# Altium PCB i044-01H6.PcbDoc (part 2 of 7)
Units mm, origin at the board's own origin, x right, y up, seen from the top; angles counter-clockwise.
Board outline 42 x 29.01 mm, 8 copper layers (Top Layer, Mid-Layer 1, Mid-Layer 2, Mid-Layer 3, Mid-Layer 4, Mid-Layer 5, Mid-Layer 6, Bottom Layer), stack 1.474 mm thick; 235 components, 197 nets, 1006 pads, 1183 vias.
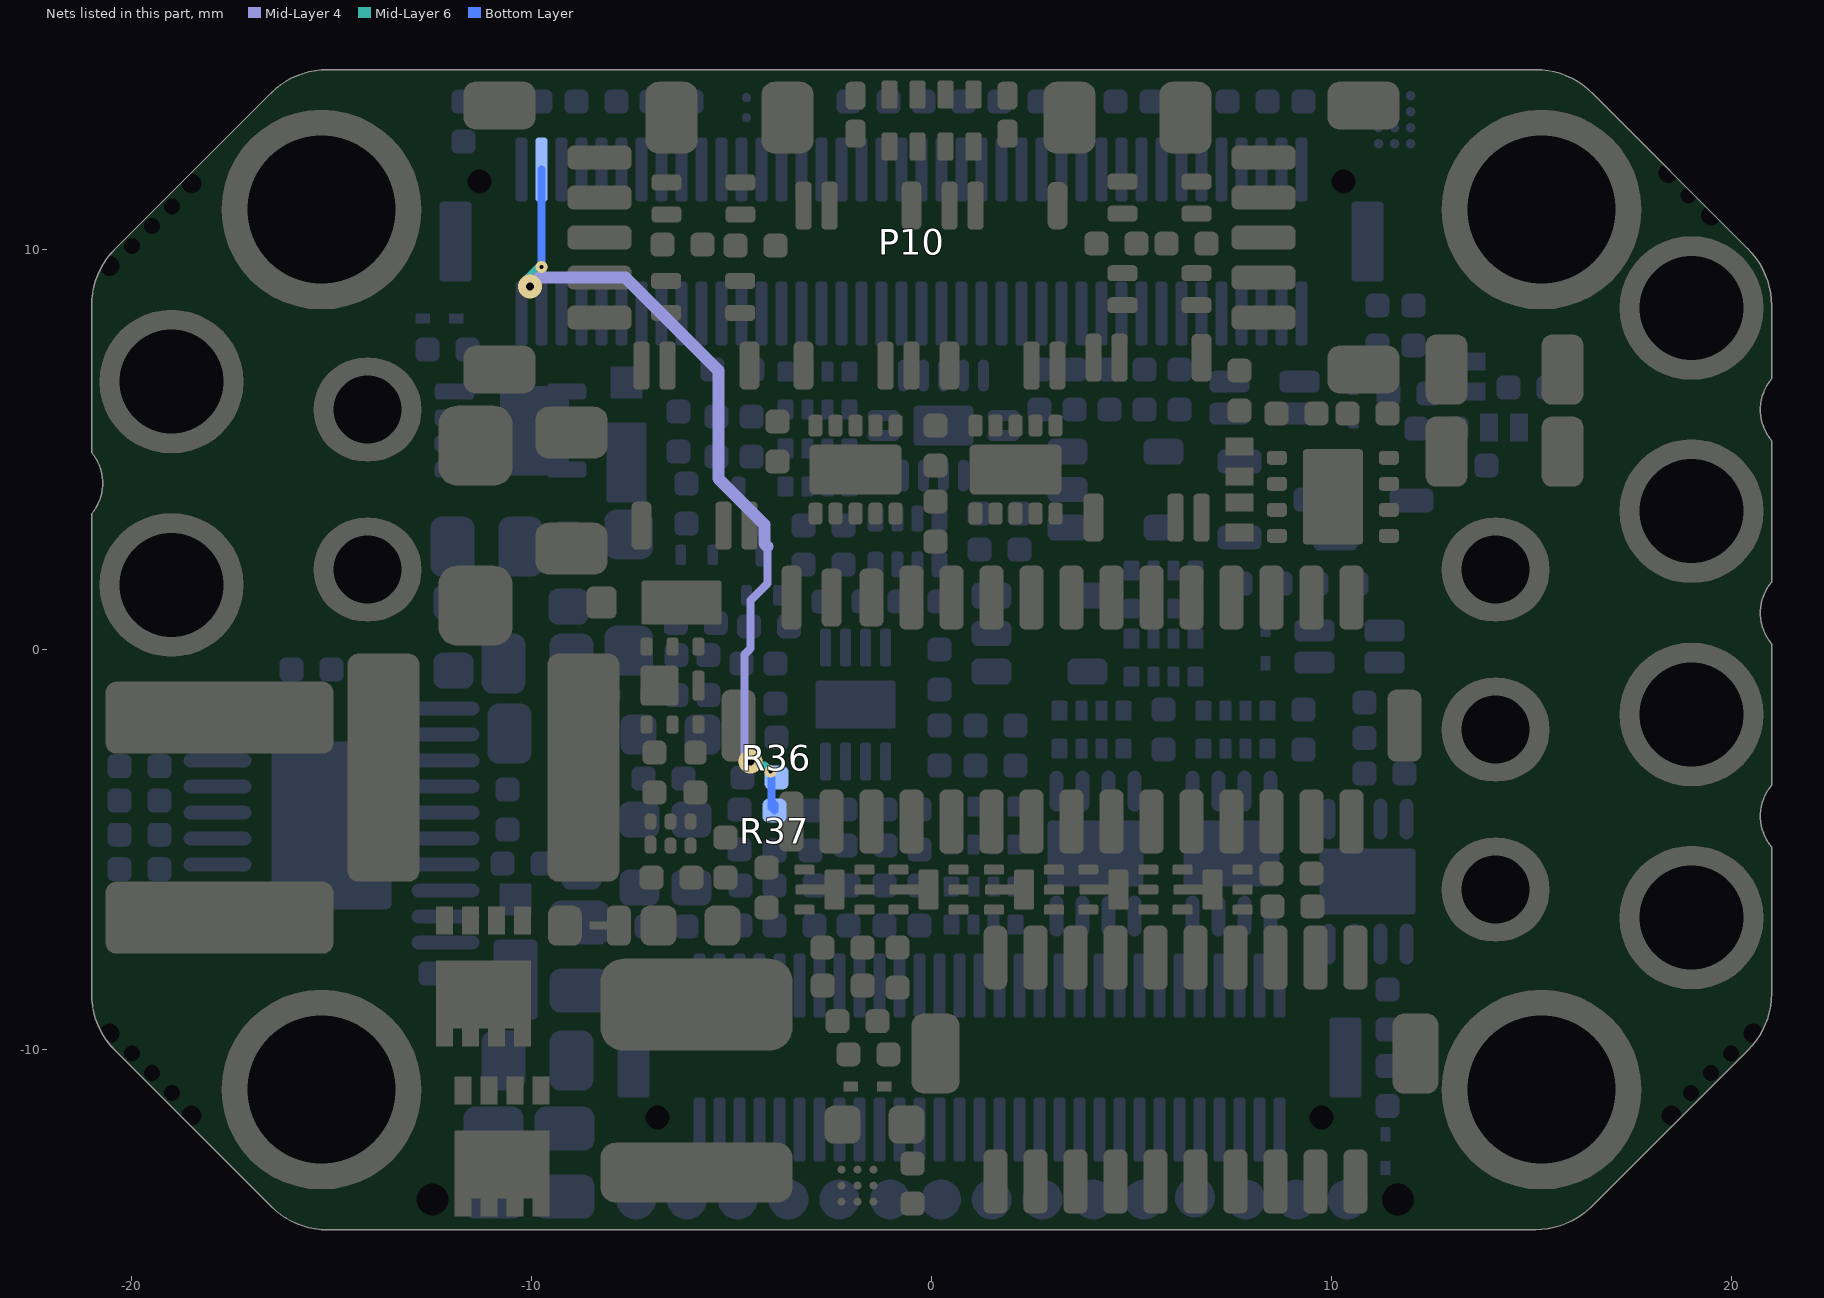
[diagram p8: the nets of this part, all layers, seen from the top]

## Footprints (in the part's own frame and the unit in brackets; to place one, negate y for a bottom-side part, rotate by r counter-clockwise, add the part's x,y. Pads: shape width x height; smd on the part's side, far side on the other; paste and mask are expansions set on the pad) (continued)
SOD923 [mm] "Doide SOD 923"
  rrect10% 0.36x0.25 smd mask+0.07: 1(-0.42,0) 2(0.42,0)
  silkscreen extent 0.9,-0.2 0.9,0.2, body extent -0.5,-0.3 0.5,0.3, height 0.4
SOD-882 [mm] "SOD-882, 2-Leads, Body 0,60x1,00mm, Pitch 0,65mm, IPC Medium Density"
  rect 0.45x0.7 smd mask+0.05: 1(-0.375,0) 2(0.375,0)
  body extent -0.55,-0.35 0.55,0.35, height 0.6
SOLDERPAD_2.6MM_EDGE [mm]
  round 3.6 hole 2.6 mask+0.05: 1(0,0)
  Multi-Layer region: -1.801,0 -1.801,1.899 -1.7,2 1.7,2 1.8,1.9 1.8,0
  body extent -0.01,-0.01 0.01,0.01, height 0.01
SOT23-3N [mm] "SOT23, 3-Leads, Body 2.9x1.3mm, Pitch 0.95mm, Lead Span 2.5mm, IPC Medium Density"
  rrect50% 1.1x0.6 smd: 1(-0.95,0.95) 2(-0.95,-0.95) 3(0.95,0)
  silkscreen extent -1.05,1.6 -0.85,1.8, body extent -1.23,-1.46 1.25,1.46, height 1
SOT23-5N [mm] "SOT23, 5-Leads, Body 2.9x1.6mm, Pitch 0.95mm, Lead Span 2.8mm, IPC Medium Density"
  rrect50% 1x0.65 smd mask+0.1: 1(-1.2,0.95) 3(-1.2,-0.95) 4(1.2,-0.95) 5(1.2,0.95)
  rrect50% 1x0.625 smd mask+0.1: 2(-1.2,0)
  silkscreen extent -1.35,1.58 -1.15,1.77, body extent -1.25,-1.5 1.25,1.5, height 1.05
SOT-723#1 [mm] "SOTFL, 3-Leads, Body 1,20x1,20mm, Pitch 0,40mm, IPC High Density"
  rrect50% 0.52x0.27 smd mask+0.07: 1(-0.49,0.4) 2(-0.49,-0.4)
  rrect65% 0.52x0.36 smd mask+0.07: 3(0.49,0)
  silkscreen extent -0.65,0.8 -0.45,1, body extent -0.59,-0.62 0.46,0.63, height 0.45
SOT-723#2 [mm] "SOTFL, 3-Leads, Body 1,20x1,20mm, Pitch 0,40mm, IPC High Density"
  rrect50% 0.52x0.27 smd mask+0.07: 1(-0.49,0.4) 2(-0.49,-0.4)
  rrect50% 0.52x0.36 smd mask+0.07: 3(0.49,0)
  silkscreen extent -0.65,0.8 -0.45,1, body extent -0.59,-0.62 0.46,0.63, height 0.45
TDK_ALT4523#1 [mm]
  rrect50% 1.2x0.41 smd: 1(-2,-1.35) 2(-2,-0.7) 4(2,1.35) 5(2,0.7)
  rrect50% 1.2x0.5 smd: 3(-2,1.35) 6(2,-1.35)
  silkscreen extent -3.4,-1.45 -3.15,-1.2, body extent -2.3,-1.6 2.3,1.6, height 2.9
TDK_ALT4523#2 [mm]
  rrect50% 1.2x0.39 smd: 1(-2,-1.35)
  rrect50% 1.2x0.41 smd: 2(-2,-0.7) 4(2,1.35) 5(2,0.7)
  rrect50% 1.2x0.5 smd: 3(-2,1.35)
  rrect50% 1.2x0.49 smd: 6(2,-1.35)
  silkscreen extent -3.4,-1.45 -3.15,-1.2, body extent -2.3,-1.6 2.3,1.6, height 2.9
TDK_ALT4523#3 [mm]
  rrect50% 1.2x0.4 smd: 1(-2,-1.35)
  rrect50% 1.2x0.41 smd: 2(-2,-0.7) 5(2,0.7)
  rrect50% 1.2x0.49 smd: 3(-2,1.35)
  rrect50% 1.2x0.39 smd: 4(2,1.35)
  rrect70% 1.19x0.5 smd: 6(2,-1.35)
  silkscreen extent -3.4,-1.45 -3.15,-1.2, body extent -2.3,-1.6 2.3,1.6, height 2.9
TDK_ALT4523#4 [mm]
  rrect50% 1.2x0.41 smd: 1(-2,-1.35) 2(-2,-0.7) 5(2,0.7)
  rrect50% 1.2x0.5 smd: 3(-2,1.35)
  rrect50% 1.2x0.39 smd: 4(2,1.35)
  rrect50% 1.19x0.5 smd: 6(2,-1.35)
  silkscreen extent -3.4,-1.45 -3.15,-1.2, body extent -2.3,-1.6 2.3,1.6, height 2.9
TSOP20_065P_EP [mm] "TSOP, 20-Leads, with Exposed Pad, Body 6.5x4.4mm, Pitch 0.65mm, IPC Medium Density"
  oval 1.7x0.35 smd: 1(-2.85,2.925) 2(-2.85,2.275) 3(-2.85,1.625) 4(-2.85,0.975) 5(-2.85,0.325) 6(-2.85,-0.325) 7(-2.85,-0.975) 8(-2.85,-1.625) 9(-2.85,-2.275) 10(-2.85,-2.925) 11(2.85,-2.925) 12(2.85,-2.275) 13(2.85,-1.625) 14(2.85,-0.975) 15(2.85,-0.325) 16(2.85,0.325) 17(2.85,0.975) 18(2.85,1.625) 19(2.85,2.275) 20(2.85,2.925)
  rrect10% 3x4.2 smd paste-3: 21(0,0)
  silkscreen extent -2.9,3.4 -2.8,3.5, body extent -3.23,-3.25 3.23,3.25, height 1.2
VSON-8_(DFN-8)_NOVIAS [mm] "8-PVSON / 8-DFN 3 x 3 mm with exposed pad, but without vias on it"
  rrect10% 1.65x2.4 smd paste-3: 0(0,0)
  rrect100% 1.025x0.35 smd paste-0.025 mask+0.07: 1(-1.562,0.975) 2(-1.562,0.325) 3(-1.562,-0.325) 4(-1.562,-0.975) 5(1.562,-0.975) 6(1.562,-0.325) 7(1.562,0.325) 8(1.562,0.975)
  silkscreen extent -2.2,1.4 -1.95,1.65, body extent -1.55,-1.5 1.55,1.5, height 1.05
WLCSP12 [mm] "BGA, 12-Leads, Body 1.36x1.66mmx0.55mm, Pitch 0.40mm"
  round 0.24 smd paste+0.015 mask+0.04: A1(-0.4,0.6) A2(0,0.6) A3(0.4,0.6) B1(-0.4,0.2) B2(0,0.2) B3(0.4,0.2) C1(-0.4,-0.2) C2(0,-0.2) C3(0.4,-0.2) D1(-0.4,-0.6) D2(0,-0.6) D3(0.4,-0.6)
  silkscreen extent -0.83,0.89 -0.73,0.98, body extent -0.68,-0.83 0.68,0.83, height 0.55
WURTH_9774030951R_SMALL [mm]
  round 5.6 / inner round 4 / far side round 5 hole 3.7 paste-403.566 mask+0: 1(0,0)
  body extent -2.55,-2.55 2.55,2.55, height 3.01

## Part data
BRK1 BRK2 BRK4: "3.4 mm break away vias", Package Type=NO, TemperatureMaxC=0
BRK3: "Small 2 mm break away holes (ONLY WHEN SPACE IS LIMITTED)", Package Type=NO, TemperatureMaxC=200, TemperatureMinC=-60
C1 C2: library part C_2420_2STACK[[/\]]15uF[[/\]]100V/X7R, "15µF 100V Ceramic Capacitor X7R Stacked SMD, 2 J-Lead (6.10mm x 5.30mm)", AlternativeManufacturer="TDK Corporation", Manufacturer3=Murata, ManufacturerPartNumber3=KCM55WR72A156MH01K, ManufacturerPN=KRM55WR72A156MH01K, Package Name="Stacked SMD, 2 J-Lead 6.10mm x 5.30mm", Package Type=SM, Part Number=C_2420_2STACK, Supplier Part Number 1=490-5787-6-ND, TemperatureMaxC=125, TemperatureMinC=-55, Voltage=100V/X7R
C3 C11: library part C_1206[[/\]]1000pF[[/\]]2000V, "CAP CERM 1000PF 2000V X7R", AlternativeManufacturer="Knowles Syfer", Manufacturer3="AVX Corporation", Manufacturer4=KEMET, ManufacturerPartNumber3=1206GC102KAZ1A, ManufacturerPartNumber4=C1206X102KGRACTU, ManufacturerPartNumber5=C1206X102KGRACAUTO, ManufacturerPN=1206Y2K00102KST, Package Name=C_1206, Package Type=SM, TemperatureMaxC=125, TemperatureMinC=-55, Voltage=2000V
C4 C6 C53: library part C_0603[[/\]]10uF[[/\]]10V/X7T, "CAP CER 10uF 10V X7T 0603 0.8mm MAX height", AlternativeManufacturer="Murata Electronics North America", ManufacturerName=Murata, ManufacturerPN=GRM188D71A106MA73D, Package Name="0603 0.80mm max height", Package Type=SM, Part Number=C_0603, Supplier Part Number 1=490-7200-1-ND, TemperatureMaxC=125, TemperatureMinC=-55, Voltage=10V/X7T
C5 C7 C10 C12: library part C_0402[[/\]]100nF[[/\]]16V, "CAP CER 100nF 16V X7R 0402", AlternativeManufacturer=Wurth, Manufacturer3=Murata, Manufacturer5=Samsung, ManufacturerName="Samsung Electro-Mechanics", ManufacturerPartNumber3=GCM155R71C104KA55D, ManufacturerPartNumber4=GCM155R71C104KA55J, ManufacturerPartNumber5=CL05B104KO5NFNC, ManufacturerPN=CL05B104KO5VPNC, Package Name=C_0402, Package Type=SM, TemperatureMaxC=125, TemperatureMinC=-55, Voltage=16V
C8 C9: library part C_0402[[/\]]1uF[[/\]]10V, "Capacitor 1uF 10V Ceramic X7S 0402", AlternativeManufacturer=Murata, ManufacturerName="TDK Corporation", ManufacturerPartNumber3=GRM155C71A105KE11D, ManufacturerPN=C1005X7S1A105K050BC, Package Name=C_0402, Package Type=SM, TemperatureMaxC=125, TemperatureMinC=-55, Voltage=10V
C13 C14 C15 C16 C17 C19 C21 C22 C23 C25 C26 C32 C35 C48 C56 C57: library part C_0402[[/\]]100nF[[/\]]16V, "CAP CER 100nF 16V X7R 0402", AlternativeManufacturer=Wurth, Manufacturer3=Murata, Manufacturer5=Samsung, ManufacturerPartNumber3=GCM155R71C104KA55D, ManufacturerPartNumber4=GCM155R71C104KA55J, ManufacturerPartNumber5=CL05B104KO5NFNC, ManufacturerPN=GRM155R71C104KA88D, Package Name=C_0402, Package Type=SM, Supplier Part Number 1=1276-6844-6-ND, SupplierPartNumber4=490-7998-1-ND, SupplierPartNumber5=1276-1508-1-ND, TemperatureMaxC=125, TemperatureMinC=-55, Voltage=16V
C18 C20: library part C_0402[[/\]]10nF[[/\]]50V, "CAP CER 10nF 50V X7R 0402", AlternativeManufacturer=KEMET, Manufacturer3=Yageo, Manufacturer4="Murata Electronics", Manufacturer5="TDK Corporation", ManufacturerName="Samsung Electro-Mechanics", ManufacturerPartNumber3=CC0402KRX7R9BB103, ManufacturerPartNumber4=GRM155R71H103KA88J, ManufacturerPartNumber5=C1005X8R1H103K050BB, ManufacturerPN=CL05B103KB5NNNC, Package Name=C_0402, Package Type=SM, TemperatureMaxC=125, TemperatureMinC=-55, Voltage=50V
C24: library part C_0402[[/\]]1uF[[/\]]6.3V, "Capacitor 1uF 6.3V Ceramic X7S 0402", AlternativeManufacturer=Murata, Manufacturer3="Murata Electronics", ManufacturerName="TDK Corporation", ManufacturerPartNumber3=GRM155R70J105KA12J, ManufacturerPartNumber4=GCM155C71A105ME38D, ManufacturerPN=CGB2A1X7S0J105M033BC, Package Name=C_0402, Package Type=SM, Supplier Part Number 1=810-CGB2A1X7S0J105MC, SupplierPartNumber4=490-18202-1-ND, TemperatureMaxC=125, TemperatureMinC=-55, Voltage=6.3V
C27 C28 C30: library part C_0402[[/\]]1nF[[/\]]50V/NP0, "MLCC, 0402, NP0, 50V, 1NF, 5%", AlternativeManufacturer=Murata, Manufacturer3=KEMET, Manufacturer4=Kemet, Manufacturer5=TDK, ManufacturerPartNumber3=C0402H102J5GACT500, ManufacturerPartNumber4=C0402C102F5GACTU, ManufacturerPartNumber5=C1005C0G2A102J050BC, ManufacturerPN=C1005NP01H102J050BA, Package Name=C_0402, Package Type=SM, Supplier Part Number 1=1292-1244-6-ND, SupplierPartNumber4=399-19359-6-ND, SupplierPartNumber5=399-8940-6-ND, TemperatureMaxC=125, TemperatureMinC=-55, Voltage=50V/NP0
C29 C31 C33 C34 C45: library part C_0402[[/\]]10nF[[/\]]50V, "CAP CER 10nF 50V X7R 0402", AlternativeManufacturer="TDK Corporation", Manufacturer3=Yageo, Manufacturer4="Murata Electronics", Manufacturer5="Samsung Electro-Mechanics", ManufacturerName=KEMET, ManufacturerPartNumber3=CC0402KRX7R9BB103, ManufacturerPartNumber4=GRM155R71H103KA88J, ManufacturerPartNumber5=CL05B103KB5NNNC, ManufacturerPN=C0402C103K5RACTU, Package Name=C_0402, Package Type=SM, Supplier Part Number 1=399-3066-1-ND, SupplierPartNumber4=490-6351-6-ND, SupplierPartNumber5=1276-1028-6-ND, TemperatureMaxC=125, TemperatureMinC=-55, Voltage=50V
C36 C37 C39 C43: library part C_0402[[/\]]100pF[[/\]]50V, "CAP CER 100pF 50V NP0/C0G 0402", AlternativeManufacturer=Kemet, Manufacturer3=Murata, ManufacturerName=Yageo, ManufacturerPartNumber3=GRM1555C1H101FA01D, ManufacturerPartNumber4=GRM1555C1H101FA01J, ManufacturerPartNumber5=C0402H101J5GACT500, ManufacturerPN=CC0402JRNPO9BN101, Package Name=C_0402, Package Type=SM, Supplier Part Number 1=311-1024-1-ND, SupplierPartNumber4=490-7753-6-ND, SupplierPartNumber5=399-13254-1-ND, TemperatureMaxC=125, TemperatureMinC=-55, Voltage=50V
C38 C52 C54 C58 C59 C60: library part C_0805[[/\]]1uF[[/\]]100V/X7S, "MLCC, 1uF 100V X7S Boardflex 1.45mm max height", AlternativeManufacturer="TDK Corporation", Manufacturer4=Murata, ManufacturerPartNumber3=C2012X7S2A105K125AB, ManufacturerPartNumber4=GRJ21BC72A105KE11L, ManufacturerPartNumber5=CGA4J3X7S2A105M125AE, ManufacturerPN=C2012X7S2A105K125AE, Package Name=C_0805, Package Type=SM, Supplier Part Number 1=445-8887-6-ND, SupplierPartNumber4=490-10918-6-ND, TemperatureMaxC=125, TemperatureMinC=-55, Voltage=100V/X7S
C40: library part C_0402[[/\]]680pF[[/\]]50V/C0G, "CAP CER 680pF 50V C0G 5% 0402", AlternativeManufacturer=Murata, Manufacturer3=KEMET, ManufacturerPartNumber3=C0402C681J5GACAUTO, ManufacturerPN=GCM1555C1H681JA16D, Package Name="C_0402 0.5mm height", Package Type=SM, Part Number=C_0402, Supplier Part Number 1=490-16438-6-ND, TemperatureMaxC=125, TemperatureMinC=-55, Voltage=50V/C0G
C41 C44 C49 C50: library part C_0402[[/\]]1uF[[/\]]10V, "Capacitor 1uF 10V Ceramic X7S 0402", AlternativeManufacturer=Murata, ManufacturerName="TDK Corporation", ManufacturerPartNumber3=GRM155C71A105KE11D, ManufacturerPN=C1005X7S1A105K050BC, Package Name=C_0402, Package Type=SM, Supplier Part Number 1=445-9116-1-ND, TemperatureMaxC=125, TemperatureMinC=-55, Voltage=10V
C42: library part C_0805[[/\]]1uF[[/\]]100V/X7S, "MLCC, 1uF 100V X7S Boardflex 1.45mm height", AlternativeManufacturer="TDK Corporation", Manufacturer4=Murata, ManufacturerPartNumber3=C2012X7S2A105K125AB, ManufacturerPartNumber4=GRJ21BC72A105KE11L, ManufacturerPartNumber5=CGA4J3X7S2A105M125AE, ManufacturerPN=C2012X7S2A105K125AE, Package Name=C_0805, Package Type=SM, Supplier Part Number 1=445-8887-6-ND, SupplierPartNumber4=490-10918-6-ND, TemperatureMaxC=125, TemperatureMinC=-55, Voltage=100V/X7S
C46: library part C_0603[[/\]]100nF[[/\]]100V/X7S, "CAP CER 100nF 100V X7S 0603 0.8mm MAX height", AlternativeManufacturer="TDK Corporation", Manufacturer3="Murata Electronics", Manufacturer4=TDK, ManufacturerPartNumber3=GRM188R72A104KA35D, ManufacturerPartNumber4=CGA3E3X7S2A104M080AB, ManufacturerPartNumber5=CGA3E3X7S2A104K080AB, ManufacturerPN=CGJ3E3X7S2A104K080AA, Package Name="0603 0.80mm max height", Package Type=SM, Part Number=C_0603, Supplier Part Number 1=445-9154-1-ND, SupplierPartNumber4=445-12576-6-ND, SupplierPartNumber5=445-6938-6-ND, TemperatureMaxC=125, TemperatureMinC=-55, Voltage=100V/X7S
C47: library part C_0402[[/\]]18pF[[/\]]50V, "CAP CER 18pF 50V C0G 0402", AlternativeManufacturer="Samsung ElectroMechanics", Manufacturer3="Murata Electronics North America", Manufacturer4=Samsung, Manufacturer5=Murata, ManufacturerName=Yageo, ManufacturerPartNumber3=GRM1555C1H180GA01D, ManufacturerPartNumber4=CL05C180JB5NNNC, ManufacturerPartNumber5=GJM1555C1H180GB01D, ManufacturerPN=CC0402FRNPO9BN180, Package Name=C_0402, Package Type=SM, Supplier Part Number 1=311-1650-1-ND, SupplierPartNumber4=1276-1140-6-ND, SupplierPartNumber5=490-8082-6-ND, TemperatureMaxC=125, TemperatureMinC=-55, Voltage=50V
C51: library part C_0402[[/\]]47nF[[/\]]25V, "CAP CER 47nF 25V X7R 10% 0402", AlternativeManufacturer="TDK Corporation", Manufacturer3="Murata Electronics", Manufacturer4=Wurth, Manufacturer5=KEMET, ManufacturerName="TAIYO YUDEN", ManufacturerPartNumber3=GCM155R71E473KA55D, ManufacturerPartNumber4=885012205054, ManufacturerPartNumber5=C0402C473K3RACTU, ManufacturerPN=TMK105B7473KV-F, Package Name=C_0402, Package Type=SM, Supplier Part Number 1=963-TMK105B7473KV-F, SupplierPartNumber4=732-7549-1-ND, SupplierPartNumber5=399-7802-1-ND, TemperatureMaxC=125, TemperatureMinC=-55, Voltage=25V
D1: "DIODE TVS 70V 400W Unidirectional 100V Clamping", ManufacturerName="Diodes Inc.", ManufacturerPN=SMAT70A-13-F, Package Name=SMA/DO-214AC, Package Type=SM, Supplier Part Number 1=SMAT70A-FDIDKR-ND, TemperatureMaxC=150, TemperatureMinC=-55
D2 D6 D10 D11 D12: "DIODE TVS 5 channel unidirectional 5V working 12.5V clamping", ManufacturerName=Vishay, Package Name="6-UFDFN Exposed Pad", Package Type=SM, Supplier Part Number 1=GMF05C-HSF-GS08CT-ND, TemperatureMaxC=125, TemperatureMinC=-55
D3 D8: "Steering/TVS diode 4x array 3.3V, 20A(8/20us) 300W, low capacitance (Ethernet)", AlternativeManufacturer=Bourns, ManufacturerName=Littlefuse, Package Name="10-UDFN (2.6x2.6)", Package Type=SM, Supplier Part Number 1=F5772CT-ND, TemperatureMaxC=125, TemperatureMinC=-40
D4 D9: "GREEN LED CLEAR LENS 2.1Vf 120º Angle 0402", AlternativeManufacturer=SunLED, ManufacturerName=Kingbright, ManufacturerPN=APHHS1005CGCK, Package Name=0402, Package Type=SM, Supplier Part Number 1=754-1101-6-ND, TemperatureMaxC=85, TemperatureMinC=-40
D5 D7: "GREEN and RED LED vertical", ManufacturerName="Broadcom Limited", ManufacturerPN=HSMF-C165, Package Name=D_0603, Package Type=SM, Supplier Part Number 1=516-1419-1-ND, TemperatureMaxC=85, TemperatureMinC=-40
D13 D14: "TVS Diode Bidirectional 24V working, 50V clamping,3A (8/20µs), 200W pk", AlternativeManufacturer=Littlefuse, ManufacturerName=Littelfuse, Package Name=SOD-882, Package Type=SM, Supplier Part Number 1=F6509TR-ND, TemperatureMaxC=125, TemperatureMinC=-40
D15 D22: "TVS Diode Bidirectional 36V working, 65V clamping,2A (8/20µs), 200W pk", AlternativeManufacturer="Littelfuse Inc.", ManufacturerPN=SPHV36-01ETG-C, Package Name=SOD-882, Package Type=SM, TemperatureMaxC=125, TemperatureMinC=-40
D16 D17: "Zener Diode 6.2V 60ohm SOD-923", AlternativeManufacturer="ON Semiconductor", Manufacturer3="Diodes Incorporated", ManufacturerPartNumber3=DZ9F6V2S92-7, ManufacturerPartNumber4=SZNZ9F6V2T5G, Package Name=SOD-923, Package Type=SM, Supplier Part Number 1=NZ9F6V2T5GOSDKR-ND, SupplierPartNumber4=SZNZ9F6V2T5GOSDKR-ND, TemperatureMaxC=150, TemperatureMinC=-65
D18 D21: "DIODE SCHOTTKY 120V 2A MICROSMP", AlternativeManufacturer=Vishay, ManufacturerPartNumber3=V2PM15HM3/H, ManufacturerPartNumber4=V2PM15-M3/H, Package Name=MICROSMP, Package Type=SM, Supplier Part Number 1=V2PM12HM3/HGIDKR-ND, SupplierPartNumber4=V2PM15-M3/HGIDKR-ND, TemperatureMaxC=175, TemperatureMinC=-40
D19: "DIODE SCHOTTKY 120V 2A MICROSMP", AlternativeManufacturer=Vishay, ManufacturerPartNumber3=V2PM15HM3/H, ManufacturerPartNumber4=V2PM15-M3/H, Package Name=MICROSMP, Package Type=SM, TemperatureMaxC=175, TemperatureMinC=-40
D20: "Diode Standard 200V 2A Low Leakage SOD-123FL", AlternativeManufacturer="On Semiconductor", ManufacturerName="ON Semiconductor", Package Name=SOD-123FL, Package Type=SM, Supplier Part Number 1=NHP220SFT3GOSCT-ND, TemperatureMaxC=175, TemperatureMinC=-65
D23 D24: "Diode High Speed 100V 200mA SOD923", AlternativeManufacturer="Central Semiconductor Corp", ManufacturerName="ON Semiconductor", Package Name=SOD-923, Package Type=SM, TemperatureMaxC=150, TemperatureMinC=-55
D25: "Diode High Speed 100V 200mA SOD923", AlternativeManufacturer="Central Semiconductor Corp", ManufacturerName="ON Semiconductor", Package Name=SOD-923, Package Type=SM, Supplier Part Number 1=BAS16P2T5GOSDKR-ND, TemperatureMaxC=150, TemperatureMinC=-55
D26: "TVS diode 5V 6.2V breakdown min 12Vclamping 9A(8/20us)", AlternativeManufacturer="ON Semiconductor", Manufacturer3="Diodes Incorporated", ManufacturerPartNumber3=D5V0M1U2S9-7, Package Name=SOD-923, Package Type=SM, Supplier Part Number 1=ESD9X5.0ST5GOSDKR-ND, TemperatureMaxC=150, TemperatureMinC=-65
FD1 FD2 FD3 FD4 FD5 FD6: "Single layer fiducial point for the PCB. 1 mm copper diameter 3 mm total diameter.", ManufacturerName=-, TemperatureMaxC=200, TemperatureMinC=-65
FD7 FD8 FD9 FD10: "Double layer fiducial point for the panel", ManufacturerName=-, TemperatureMaxC=200, TemperatureMinC=-60
H1 H2 H3 H4 H5 H6: library part Solderpad_2.6mm_Edge, "plated hole for edge of the board, 2.6 mm diameter for soldering cables up to 10 AWG", Package Name=-, Package Type=NO, TemperatureMaxC=-55, TemperatureMinC=200
L1: library part L_SRN6045[[/\]]47uH, "INDUCTOR, 47uH 20%, 200mohm DCR, 1.6A rating 2A saturation, 6mmx6mm semi-shielded", ManufacturerName=Bourns, ManufacturerPN=SRN6045TA-470M, Package Name="SMD 6x6mm 4.50mm height", Package Type=SM, Part Number=L_SRN6045, Supplier Part Number 1=SRN6045TA-470MDKR-ND, TemperatureMaxC=125, TemperatureMinC=-55
L2 L3 L5 L6: library part SRF2012A-900YA[[/\]]90Z, "2 Line 2 Line Common Mode Choke 125ºC 90Ohms 50V @100MHz 370mA DCR 300 mOhm for LAN", AlternativeManufacturer=Wurth, Manufacturer3="Laird-Signal Integrity Products", Manufacturer4="Bourns Inc.", ManufacturerName=Bourns, ManufacturerPartNumber3=CM0805D900R-10, ManufacturerPartNumber4=SRF2012-900YA, Package Name="SMD choke 4 pins 0805 No polarity", Package Type=SM, TemperatureMaxC=125, TemperatureMinC=-40
L4 L7 L8: library part L_0402[[/\]]1000Z, "FERRITE BEAD, 0402 CASE, 200mA, Wideband", AlternativeManufacturer=Murata, Manufacturer3=TDK, ManufacturerPartNumber3=MMZ1005S102CTD25, ManufacturerPN=MMZ1005S102CT000, Package Type=SM, Supplier Part Number 1=810-MMZ1005S102CT000, TemperatureMaxC=125, TemperatureMinC=-55
L9 L10: library part L_0603[[/\]]470Z/1A, "Ferrite Bead 470ohm 100MHz, 1A 150mOhm", AlternativeManufacturer=TDK, Manufacturer3="TDK Corporation", Manufacturer5="Taiyo Yuden", ManufacturerPartNumber3=MPZ1608S471ATD25, ManufacturerPartNumber4=MPZ1608B471ATD25, ManufacturerPartNumber5=FBMH1608HM471-T, ManufacturerPN=MPZ1608B471ATA00, Package Type=SM, Supplier Part Number 1=445-5218-1-ND, SupplierPartNumber4=445-172884-6-ND, SupplierPartNumber5=587-1744-6-ND, TemperatureMaxC=125, TemperatureMinC=-55
L11 L12: library part FB_0603[[/\]]220Z/2.5A, "Ferrite Bead 220Ohm@100MHz 2.5A DC, 40mOhm, -55ºC ~ 125ºC 0603", ManufacturerName=Murata, ManufacturerPN=BLM18SG221TN1D, Package Name="0603 (1608 Metric)", Package Type=SM, Supplier Part Number 1=490-5225-6-ND, TemperatureMaxC=125, TemperatureMinC=-55
LABEL1: "Space for PCB Label on silkscreen (preferred) or Assembly layer only", ManufacturerName=IngeniaLabels, ManufacturerPN=25, Package Type=NO, Supplier Part Number 1=-, TemperatureMaxC=200, TemperatureMinC=-65
LAYERS1: "8 layers stackup legend small", Package Name=None, Package Type=SM
M1 M2 M3 M4: "Round SMD standoff M2.5 3mm height No Threaded Steel", ManufacturerName="Wurth Electronics Inc", ManufacturerPN=9774030951R, Package Name="SPACER M2.5 SMD REEL 3MM", Package Type=SM, Supplier Part Number 1=732-7086-1-ND, TemperatureMaxC=200, TemperatureMinC=-40
NT1: "Net-Tie, Surface Mount, 1.2mm x 0.2mm", Package Name=-, Package Type=NO
ORIGIN1: "Origin of coordinate axes for pick and place", ManufacturerName=-, TemperatureMaxC=200, TemperatureMinC=-60
P1 P2 P7 P8 P9: "1.65mm hole TH PAD", Package Name=-, Package Type=NO
P3 P6: "Male shrouded header, SM, 5 ways vertical, 1 mm pitch", AlternativeManufacturer=Molex, ManufacturerPartNumber3=501940-0507-TR275, ManufacturerPN=5019400507, Package Name="5 way Pico-Clasp 501940", Package Type=SM, Supplier Part Number 1=WM14444CT-ND, TemperatureMaxC=105, TemperatureMinC=-40
P4: "Male shrouded header, SM, 15x2 ways vertical, 1 mm pitch", AlternativeManufacturer=Molex, ManufacturerPN=501190-3017, Package Name=SH_Header_30_pin_1m, Package Type=SM, Supplier Part Number 1=WM7908DKR-ND, TemperatureMaxC=105, TemperatureMinC=-40
P5: "Male shrouded header, SM, 20 ways vertical, 1 mm pitch", AlternativeManufacturer=Molex, ManufacturerPartNumber3=5011902017, ManufacturerPN=5011902027, Package Name="20 way Pico-Clasp 501190", Package Type=SM, Supplier Part Number 1=WM12955CT-ND, TemperatureMaxC=105, TemperatureMinC=-40
P10: "Connector SMD Mezzanine, 80 ways, 0.5mm pitch, 3mm stack height. Male with metal fitting and boss", ManufacturerName=Hirose, ManufacturerPN=DF12(3.0)-80DS-0.5V(86), Package Name="SMD connector 80 ways male", Package Type=SM, Supplier Part Number 1=H5208CT-ND, TemperatureMaxC=125, TemperatureMinC=-45
P11: "Connector SMD Mezzanine, 60 ways, 0.5mm pitch, 3mm stack height. Male", ManufacturerName=Hirose, ManufacturerPN=DF12(3.0)-60DS-0.5V(86), Package Name="SMD connector 60 ways", Package Type=SM, Supplier Part Number 1=H5207CT-ND, TemperatureMaxC=125, TemperatureMinC=-45
Q1: "MOSFET N-CH 100V, 3.5A 6-UDFNB, 2X2 2.5Vgs th", AlternativeManufacturer="ON Semiconductor", ManufacturerName=Toshiba, ManufacturerPN=SSM6K361NU,LF, Package Name="6-UDFNB (2x2) / 6-WDFN Exposed Pad", Package Type=SM, Supplier Part Number 1=SSM6K361NULFDKR-ND, TemperatureMaxC=150, TemperatureMinC=-55
Q2 Q3: "MOSFET N-CH 150V 17A 8DFN 54mOhm Low Vgsth", ManufacturerName="Alpha & Omega Semiconductor Inc.", Package Name="8-DFN-EP (3.3x3.3 mm)", Package Type=SM, Supplier Part Number 1=785-1675-6-ND, TemperatureMaxC=150, TemperatureMinC=-55
Q4 Q5: "DEPLETION MOSFET N-CH 250V, 100mA, SOT23", ManufacturerName=Infineon, Package Name="SOT 23", Package Type=SM, TemperatureMaxC=150, TemperatureMinC=-55
Q6: "P-Channel MOSFET 100V 10.8A(25C Tc) PowerPAK 1212-8", AlternativeManufacturer=Vishay, ManufacturerPartNumber3=SI7113ADN-T1-GE3, ManufacturerPN=SI7113DN-T1-GE3, Package Name="PowerPAK® 1212-8", Package Type=SM, Supplier Part Number 1=SI7113DN-T1-GE3DKR-ND, TemperatureMaxC=150, TemperatureMinC=-55
Q7 Q8 Q9: "Transistor NPN 160V 60mA SOT-723", AlternativeManufacturer="On Semiconductor", Manufacturer3=-, Package Name=SOT-723, Package Type=SM, Supplier Part Number 1=MMBT5551M3T5GOSDKR-ND, TemperatureMaxC=150, TemperatureMinC=-55
R1 R49: library part R_0402[[/\]]20K[[/\]]1%, "RES 20K OHM 1/10W 1% 0402 SMD", AlternativeManufacturer=Vishay, Manufacturer3=Yageo, Manufacturer4=Samsung, Manufacturer5="Bourns Inc.", ManufacturerName="Panasonic Electronic Components", ManufacturerPartNumber3=RC0402FR-0720KL, ManufacturerPartNumber4=RCS1005F203CS, ManufacturerPartNumber5=CR0402-FX-2002GLF, ManufacturerPN=ERJ-2RKF2002X, Package Name=R_0402, Package Type=SM, Supplier Part Number 1=P20.0KLDKR-ND, SupplierPartNumber4=1276-7040-6-ND, SupplierPartNumber5=CR0402-FX-2002GLFDKR-ND, TemperatureMaxC=155, TemperatureMinC=-55, Tolerance=1%
R2 R41 R54 R57 R59 R60 R61: library part R_0402[[/\]]100K[[/\]]1%, "Resistor 100kohm  1/16W 1% 0402", AlternativeManufacturer="Bourns Inc.", Manufacturer3=Welwyn, Manufacturer4="Samsung Electro-Mechanics", Manufacturer5="Vishay Dale", ManufacturerName=Yageo, ManufacturerPartNumber3=ASC0402-100KFT10, ManufacturerPartNumber4=RC1005F104CS, ManufacturerPartNumber5=RCG0402100KFKED, ManufacturerPN=RC0402FR-07100KL, Package Name=R_0402, Package Type=SM, Supplier Part Number 1=311-100KLRDKR-ND, SupplierPartNumber4=1276-3432-6-ND, SupplierPartNumber5=541-1751-6-ND, TemperatureMaxC=155, TemperatureMinC=-55, Tolerance=1%
R3 R62: library part R_0402[[/\]]100k[[/\]]1%, "Resistor 100kohm  1/16W 1% 0402", AlternativeManufacturer="Bourns Inc.", Manufacturer3=Welwyn, Manufacturer4="Samsung Electro-Mechanics", Manufacturer5="Vishay Dale", ManufacturerName=Yageo, ManufacturerPartNumber3=ASC0402-100KFT10, ManufacturerPartNumber4=RC1005F104CS, ManufacturerPartNumber5=RCG0402100KFKED, ManufacturerPN=RC0402FR-07100KL, Package Name=R_0402, Package Type=SM, Supplier Part Number 1=311-100KLRDKR-ND, SupplierPartNumber4=1276-3432-6-ND, SupplierPartNumber5=541-1751-6-ND, TemperatureMaxC=155, TemperatureMinC=-55, Tolerance=1%
R4: "Varistor SMD 1206 100A 48VDC working 62Vtyp, clamping 100Vc 100A", AlternativeManufacturer=Littelfuse, Manufacturer3="Abracon LLC", ManufacturerName="AVX Corporation", ManufacturerPartNumber3=AMCV-1206H-480-T, Package Name=1206, Package Type=SM, Supplier Part Number 1=478-2524-6-ND, TemperatureMaxC=125, TemperatureMinC=-55
R5 R32 R33 R36 R37: library part R_0402[[/\]]1k65[[/\]]0.1%, "Reistor 1k65 1.65kohm 1/16W 0.1%", AlternativeManufacturer=Yageo, Manufacturer3="Panasonic Electronic Components", Manufacturer5="TE Connectivity Passive Product", ManufacturerName="TE connectivity", ManufacturerPartNumber3=ERA-2AEB1651X, ManufacturerPartNumber4=ERA-2APB1651X, ManufacturerPartNumber5=RN73C1E1K65BTD, ManufacturerPN=CPF0402B1K65E1, Package Name=R_0402, Package Type=SM, Supplier Part Number 1=A102693DKR-ND, SupplierPartNumber4=P17738DKR-ND, SupplierPartNumber5=A121684DKR-ND, TemperatureMaxC=155, TemperatureMinC=-55, Tolerance=0.1%
R6 R47: library part R_0402[[/\]]10K[[/\]]1%, "RESISTOR 10K OHM 1/16W 1% 0402 SMD", AlternativeManufacturer="Vishay Dale", Manufacturer3="TE Connectivity Passive Product", Manufacturer4="KOA Speer Electronics, Inc.", Manufacturer5="Panasonic Electronic Components", ManufacturerName="Stackpole Electronics", ManufacturerPartNumber3=CRGCQ0402F10K, ManufacturerPartNumber4=RK73H1ETTP1002F, ManufacturerPartNumber5=ERJ-2RKF1002X, ManufacturerPN=RMCF0402FT10K0, Package Name=R_0402, Package Type=SM, Supplier Part Number 1=RMCF0402FT10K0CT-ND, SupplierPartNumber4=2019-RK73H1ETTP1002FDKR-ND, SupplierPartNumber5=P10.0KLDKR-ND, TemperatureMaxC=155, TemperatureMinC=-55, Tolerance=1%
R7 R8: "18V varistor, 11Vworking, 16Apk 30Vclamp Varistor 0402", AlternativeManufacturer="Panasonic Electronic Components", ManufacturerName="TDK Corporation", Package Name=0402, Package Type=SM, Supplier Part Number 1=445-174349-1-ND, TemperatureMaxC=125, TemperatureMinC=-40
R9 R10 R14 R15 R51 R53: library part R_0402[[/\]]75R[[/\]]1%, "RES 75 OHM 1/16W 1% 0402 SMD", AlternativeManufacturer=Samsung, Manufacturer3=Yageo, Manufacturer4=Bourns, Manufacturer5="Vishay Dale", ManufacturerName=Panasonic, ManufacturerPartNumber3=AC0402FR-0775RL, ManufacturerPartNumber4=CR0402-FX-75R0GLF, ManufacturerPartNumber5=RCS040275R0FKED, ManufacturerPN=ERJ-2RKF75R0X, Package Name=R_0402, Package Type=SM, TemperatureMaxC=155, TemperatureMinC=-55, Tolerance=1%
R11 R12 R13 R16: library part R_0402[[/\]]220R[[/\]]1%,200mW, "Resistor 220ohm 200mW high power pulse withstanding", AlternativeManufacturer=VISHAY, Manufacturer3="Vishay Dale", ManufacturerName="Panasonic Electronic Components", ManufacturerPartNumber3=RCS0402220RFKED, ManufacturerPN=ERJ-PA2F2200X, Package Name=R_0402, Package Type=SM, Supplier Part Number 1=P17220DKR-ND, TemperatureMaxC=155, TemperatureMinC=-55, Tolerance=1%,200mW
R17 R18: library part R_1206[[/\]]1k[[/\]]1%,0.75W, "Resistor 1kohm 1% 750mW Pulse Withstanding 100ppm", AlternativeManufacturer="Vishay Dale", Manufacturer3=Yageo, ManufacturerName="Bourns Inc.", ManufacturerPartNumber3=SR1206FR-7T1KL, ManufacturerPartNumber4=CRCW12061K00FKEAHP, ManufacturerPN=CHP1206-FX-1001ELF, Package Name=R_1206, Package Type=SM, TemperatureMaxC=155, TemperatureMinC=-55, Tolerance=1%,0.75W
R19 R39 R50 R52 R55 R56: library part R_0402[[/\]]220R[[/\]]1%,200mW, "Resistor 220ohm 200mW high power pulse withstanding", AlternativeManufacturer=VISHAY, Manufacturer3="Vishay Dale", ManufacturerName="Panasonic Electronic Components", ManufacturerPartNumber3=RCS0402220RFKED, ManufacturerPN=ERJ-PA2F2200X, Package Name=R_0402, Package Type=SM, TemperatureMaxC=155, TemperatureMinC=-55, Tolerance=1%,200mW
R20 R21 R23 R24: library part R_0402[[/\]]20K[[/\]]1%, "RES 20K OHM 1/10W 1% 0402 SMD", AlternativeManufacturer=Vishay, Manufacturer3=Yageo, Manufacturer4=Samsung, Manufacturer5="Bourns Inc.", ManufacturerName="Panasonic Electronic Components", ManufacturerPartNumber3=RC0402FR-0720KL, ManufacturerPartNumber4=RCS1005F203CS, ManufacturerPartNumber5=CR0402-FX-2002GLF, ManufacturerPN=ERJ-2RKF2002X, Package Name=R_0402, Package Type=SM, TemperatureMaxC=155, TemperatureMinC=-55, Tolerance=1%
R22 R29 R45 R48: library part R_0402[[/\]]3k74[[/\]]1%, "Resistor 0402 3k74 1%, 0.063W", AlternativeManufacturer=Yageo, Manufacturer3="Stackpole Electronics", ManufacturerName="Vishay Dale", ManufacturerPartNumber3=RMCF0402FT3K74, ManufacturerPN=CRCW04023K74FKED, Package Name=R_0402, Package Type=SM, Supplier Part Number 1=71-CRCW0402-3.74K-E3, TemperatureMaxC=155, TemperatureMinC=-55, Tolerance=1%
R25 R26 R27 R28 R31: library part R_0402[[/\]]1K[[/\]]1%, "RES 1K OHM 1/16W 1% 0402 SMD", AlternativeManufacturer="KOA Speer Electronics, Inc.", Manufacturer3="Vishay Dale", Manufacturer5=Yageo, ManufacturerName="Panasonic Electronic Components", ManufacturerPartNumber3=CRCW04021K00FKEDHP, ManufacturerPartNumber4=RCA04021K00FKEDHP, ManufacturerPartNumber5=SR0402FR-7T1KL, ManufacturerPN=ERJ-2RKF1001X, Package Name=R_0402, Package Type=SM, Supplier Part Number 1=P1.00KLDKR-ND, SupplierPartNumber4=541-3240-6-ND, SupplierPartNumber5=YAG5817DKR-ND, TemperatureMaxC=155, TemperatureMinC=-55, Tolerance=1%
R30 R34 R35 R38: library part R_0402[[/\]]10K[[/\]]0.1%, "RESISTOR, 0402 0,1% 10K 1/16W", AlternativeManufacturer=Susumu, Manufacturer3="Panasonic Electronic Components", Manufacturer4=Yageo, Manufacturer5="Vishay Beyschlag", ManufacturerName="Stackpole Electronics Inc.", ManufacturerPartNumber3=ERA-2AEB103X, ManufacturerPartNumber4=AT0402BRD0710KL, ManufacturerPartNumber5=MCS0402MD1002BE100, ManufacturerPN=RNCF0402BTE10K0, Package Name=R_0402, Package Type=SM, Supplier Part Number 1=RNCF0402BTE10K0CT-ND, SupplierPartNumber4=YAG2087DKR-ND, SupplierPartNumber5=MCS0402-10.0K-MBDKR-ND, TemperatureMaxC=155, TemperatureMinC=-55, Tolerance=0.1%
R40: library part R_0603[[/\]]25mohm[[/\]]1%, "Resistor 0.025ohm 330mW 1% high power thick film", AlternativeManufacturer=Panasonic, ManufacturerPN=ERJ-3BWFR025V, Package Name="0603 0.55mm", Package Type=SM, Part Number=R_0603, Supplier Part Number 1=P17464DKR-ND, TemperatureMaxC=155, TemperatureMinC=-55, Tolerance=1%
R42: library part R_0402[[/\]]220R[[/\]]1%,200mW, "Resistor 220ohm 200mW high power", AlternativeManufacturer=VISHAY, Manufacturer3="Vishay Dale", ManufacturerName="Panasonic Electronic Components", ManufacturerPartNumber3=RCS0402220RFKED, ManufacturerPN=ERJ-PA2F2200X, Package Name=R_0402, Package Type=SM, Supplier Part Number 1=P17220DKR-ND, TemperatureMaxC=155, TemperatureMinC=-55, Tolerance=1%,200mW
R43: library part R_0402[[/\]]13K7[[/\]]1%, "Resistor 0402 13K7 1%, 0.063W", AlternativeManufacturer="KOA Speer Electronics, Inc.", Manufacturer3="Panasonic Electronic Components", Manufacturer4="Vishay Dale", ManufacturerName="Stackpole electronics", ManufacturerPartNumber3=ERJ-2RKF1372X, ManufacturerPartNumber4=CRCW040213K7FKED, ManufacturerPN=RMCF0402FT13K7, Package Name=R_0402, Package Type=SM, Supplier Part Number 1=RMCF0402FT13K7CT-ND, SupplierPartNumber4=541-13.7KLDKR-ND, TemperatureMaxC=155, TemperatureMinC=-55, Tolerance=1%
R44 R46: library part R_0402[[/\]]1K2[[/\]]1%, "RES 1K2 OHM 1/16W 1% 0402 SMD", AlternativeManufacturer="Samsung Electro-Mechanics", Manufacturer3="Vishay Dale", Manufacturer4="Panasonic Electronic Components", Manufacturer5="TE Connectivity Passive Product", ManufacturerName=Yageo, ManufacturerPartNumber3=CRCW04021K20FKEDC, ManufacturerPartNumber4=ERJ-2RKF1201X, ManufacturerPartNumber5=CRGCQ0402F1K2, ManufacturerPN=RC0402FR-071K2L, Package Name=R_0402, Package Type=SM, Supplier Part Number 1=311-1.20KLRTR-ND, SupplierPartNumber4=P1.20KLTR-ND, SupplierPartNumber5=A129628CT-ND, TemperatureMaxC=155, TemperatureMinC=-55, Tolerance=1%
R58: library part R_0402[[/\]]220k[[/\]]1%, "RES 220k 1/16W 1% 0402", AlternativeManufacturer=Yageo, Manufacturer3="TE Connectivity Passive Product", Manufacturer4="KOA Speer Electronics, Inc.", Manufacturer5="Panasonic Electronic Components", ManufacturerName=Vishay, ManufacturerPartNumber3=CRGCQ0402F220K, ManufacturerPartNumber4=RK73H1ETTP2203F, ManufacturerPartNumber5=ERJ-2RKF2203X, ManufacturerPN=CRCW0402220KFKED, Package Name=R_0402, Package Type=SM, Supplier Part Number 1=541-220KLDKR-ND, SupplierPartNumber4=2019-RK73H1ETTP2203FDKR-ND, SupplierPartNumber5=P220KLDKR-ND, TemperatureMaxC=155, TemperatureMinC=-55, Tolerance=1%
RN1 RN2 RN3: library part R_ARRAY_0804_8[[/\]]2K[[/\]]5%, "RESISTOR ARRAY4 2k 1/16W 5%", AlternativeManufacturer=Panasonic, Manufacturer3=Yageo, ManufacturerName="Vishay Dale", ManufacturerPartNumber3=YC124-JR-072KL, ManufacturerPN=CRA04S0832K00JTD, Package Name=0804-8, Package Type=SM, Part Number=R_ARRAY_0804_8, Supplier Part Number 1=CRA4S82.0KCT-ND, TemperatureMaxC=155, TemperatureMinC=-55, Tolerance=5%
RN4 RN6: library part R_ARRAY_0804_8[[/\]]1K[[/\]]1%, "RESISTOR ARRAY4 1k 1/16W 1%", AlternativeManufacturer=Yageo, Manufacturer3="CTS Resistor Products", ManufacturerName="Panasonic Electronic Components", ManufacturerPartNumber3=741X083102JP, ManufacturerPN=EXB-28V102JX, Package Name=0804-8, Package Type=SM, Part Number=R_ARRAY_0804_8, Supplier Part Number 1=Y7102CT-ND, TemperatureMaxC=155, TemperatureMinC=-55, Tolerance=1%
RN5 RN8: library part R_ARRAY_0804_8[[/\]]10K[[/\]]1%, "Resistor array 4 x 10kohm 5% 0804", AlternativeManufacturer=Bourns, ManufacturerName="Vishay Dale", ManufacturerPN=CRA04S08310K0FTD, Package Name=R_ARRAY_0804, Package Type=SM, Part Number=R_ARRAY_0804_8, Supplier Part Number 1=Y10103DKR-ND, TemperatureMaxC=155, TemperatureMinC=-55, Tolerance=1%
RN7: library part R_ARRAY_0804_8[[/\]]470R[[/\]]5%, "RESISTOR ARRAY 470R 0804 5%", AlternativeManufacturer=Panasonic, Manufacturer3="Vishay Dale", ManufacturerName=Bourns, ManufacturerPartNumber3=CRA04S083470RJTD, ManufacturerPN=CAY10-471J4LF, Package Name=0804-8, Package Type=SM, Part Number=R_ARRAY_0804_8, Supplier Part Number 1=CAY10-471J4LFCT-ND, TemperatureMaxC=125, TemperatureMinC=-55, Tolerance=5%
RN9: library part R_ARRAY_0804_8[[/\]]15K[[/\]]5%, "RESISTOR ARRAY4 15kohm 1/16W 5%", AlternativeManufacturer="CTS Resistor Products", Manufacturer3="Panasonic Electronic Components", ManufacturerName=Panasonic, ManufacturerPartNumber3=EXB-N8V153JX, ManufacturerPN=EXB-28V153JX, Package Name=0804-8, Package Type=SM, Part Number=R_ARRAY_0804_8, Supplier Part Number 1=Y7153DKR-ND, TemperatureMaxC=155, TemperatureMinC=-55, Tolerance=5%
T1 T2 T3 T4: library part ALT4532P-181-T05G[[/\]]-, "Pulse Transformer LAN 1CT:1CT 180µH 1000BASE-T/2.5GBASE-T/5GBASE-T, PoE[600mA]", ManufacturerName=TDK, Package Name="SMD 4.50mm x 3.20mm Transformer", Package Type=SM, TemperatureMaxC=105, TemperatureMinC=-40
U1: "Load switch High Side P-Channel, Current Limiting adjustable, Overtemperature 150ºC Tjunction, Reverse current, UVLO", ManufacturerName="On semiconductor", Package Name="6-UFBGA, 9-WLCSP (1.21x1.21)", Package Type=SM, Supplier Part Number 1=FPF2495UCXDKR-ND, TemperatureMaxC=150, TemperatureMinC=-40
U2: "(NRND) CAN Transceiver 1Mbps 8DFN (3x3)", AlternativeManufacturer=Microchip, Manufacturer3=MICROCHIP, ManufacturerPartNumber3=MCP2562T-H/MF, Package Name="DFN-8 (3x3 mm)", Package Type=SM, Supplier Part Number 1=MCP2562-E/MF-ND, TemperatureMaxC=125, TemperatureMinC=-40
U3 U5: "SSR SPST-NO (1 Form A), 1A, 0~20V, 4-SMD 4-VSON (1.4mm height)", ManufacturerName=Toshiba, Package Name=4-VSON, Package Type=SM, TemperatureMaxC=110, TemperatureMinC=-40
U4 U6 U8: "RS-485/422 Transceiver (1 TX/ 1 RX), 50Mbps, 3.3V", AlternativeManufacturer="Texas Instruments", Package Name=8-PVSON, Package Type=SM, Supplier Part Number 1=296-40525-1-ND, TemperatureMaxC=125, TemperatureMinC=-40
U7 U9: "Single differential line receiver RS422 RS485 52 MBps 125ºC", ManufacturerName="Maxim Integrated", Package Name=SOT23-5, Package Type=SM, Supplier Part Number 1=2085152, TemperatureMaxC=125, TemperatureMinC=-40
U10: "Quad tristate buffer, 5V supply, 3.3V input, noninverting, 14-DHVQFN", ManufacturerName=Nexperia, ManufacturerPN=74AHCT125BQ,115, Package Name=DHVQFN-14, Package Type=SM, Supplier Part Number 1=1727-6782-1-ND, TemperatureMaxC=125, TemperatureMinC=-40
U11: "OP AMP, R-R, DUAL, 10 MHz", AlternativeManufacturer="Texas Instruments", Package Name=8-WFDFN, Package Type=SM, Supplier Part Number 1=296-42090-6-ND, TemperatureMaxC=125, TemperatureMinC=-40
U12: "Triple inverter", ManufacturerName="Texas Instruments", Package Name=8-DSBGA, Package Type=SM, Supplier Part Number 1=296-15110-1-ND, TemperatureMaxC=125, TemperatureMinC=-40
U13: "Buffer Non-Inverting 1.65V to 5.5V (Schmitt trigger Inputs 3.3V ready) 6VSON push-pull output", ManufacturerName="Texas Instruments", Package Name="6-SON (1.45x1), 6-UFDFN", Package Type=SM, Supplier Part Number 1=296-21546-6-ND, TemperatureMaxC=125, TemperatureMinC=-40
U14: "100V DC/DC controller, buck synchronous", AlternativeManufacturer="Texas Instruments", ManufacturerPN=LM5116MH/NOPB, Package Name=TSOP20_065P_EP, Package Type=SM, Supplier Part Number 1=LM5116MH/NOPB-ND, TemperatureMaxC=125, TemperatureMinC=-40
U15: "Bidirectional high-side power switch", ManufacturerName=NXP, Package Name=WLCSP12, Package Type=SM, Supplier Part Number 1=568-11380-1-ND, TemperatureMaxC=125, TemperatureMinC=-40

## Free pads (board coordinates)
  round 0 hole 0.8 unplated mask+0: 0(-12.475,-13.745) 0(11.665,-13.745)
  round 1 on Mech16 paste+0 mask+0: 1(-26,0) 1(-26,39) 1(-26,78) 1(-26,117) 1(21.5,-15.5) 1(21.5,15.5) 1(21.5,23.5) 1(21.5,54.5) 1(21.5,62.5) 1(21.5,93.5) 1(21.5,101.5) 1(21.5,132.5) 1(26,0) 1(26,39) 1(26,78) 1(26,117) 1(73.5,-15.5) 1(73.5,15.5) 1(73.5,23.5) 1(73.5,54.5) 1(73.5,62.5) 1(73.5,93.5) 1(73.5,101.5) 1(73.5,132.5) 1(78,0) 1(78,39) 1(78,78) 1(78,117) 1(125.5,-15.5) 1(125.5,15.5) 1(125.5,23.5) 1(125.5,54.5) 1(125.5,62.5) 1(125.5,93.5) 1(125.5,101.5) 1(125.5,132.5)
  round 0.5 on Mech16 paste+0 mask+0: 1(0,0) 1(0,0) 1(0,39) 1(0,39) 1(0,78) 1(0,78) 1(0,117) 1(0,117) 1(52,0) 1(52,0) 1(52,39) 1(52,39) 1(52,78) 1(52,78) 1(52,117) 1(52,117) 1(104,0) 1(104,0) 1(104,39) 1(104,39) 1(104,78) 1(104,78) 1(104,117) 1(104,117)
  round 1 smd far side paste-2 mask+0.01: 4(-7.385,-13.745) 5(-6.115,-13.745) 6(-4.845,-13.745) 7(-3.575,-13.745) 8(-2.305,-13.745) 9(-1.035,-13.745) 10(0.235,-13.745) 11(1.505,-13.745) 12(2.775,-13.745) 13(4.045,-13.745) 14(5.315,-13.745) 15(6.585,-13.695) 16(7.855,-13.745) 17(9.125,-13.745) 18(10.395,-13.745)
  rrect50% 0.6x0.6 smd: 8(19,8.54)

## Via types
v1: diameter 0.3/0.3 (per signal layer), hole 0.1, Mid-Layer 6 to Bottom Layer, 515 vias
v2: diameter 0.3/0.3 (per signal layer), hole 0.1, Top Layer to Mid-Layer 1, 392 vias
v3: diameter 0.6, hole 0.2, Mid-Layer 1 to Mid-Layer 6, 276 vias

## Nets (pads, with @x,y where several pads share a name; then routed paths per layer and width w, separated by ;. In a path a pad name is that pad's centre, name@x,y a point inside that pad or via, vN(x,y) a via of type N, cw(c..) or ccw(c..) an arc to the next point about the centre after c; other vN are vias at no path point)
1.65V_REF: P10.4 R36.2 R37.1 | length 21.1
  Mid-Layer 4 w0.2: v3@-4.65,-2.9 -4.55,-2.8 v3(-4.525,-2.8) -4.675,-2.65 -4.675,-0.119 -4.525,0.031 -4.525,1.228 -4.1,1.653 -4.1,2.574
  Mid-Layer 4 w0.3: v3(-10.038,9.075) -9.813,9.3 -7.65,9.3 -5.325,6.975 -5.325,4.274 -4.175,3.124 -4.175,2.649 -4.1,2.574
  Mid-Layer 6 w0.2: v3@-4.65,-2.9 -4.175,-2.9 v1(-4.025,-3.05)
  Mid-Layer 6 w0.3: v3(-10.038,9.075) -10.038,9.275 v1(-9.75,9.562)
  Bottom Layer w0.2: v1@-9.763,9.55 v1(-9.75,9.562) P10.4@-9.75,12 ; R37.1@-4,-3.95 R36.2@-4,-3.225 ; R37.1@-3.925,-4.025 R37.1@-3.925,-3.875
